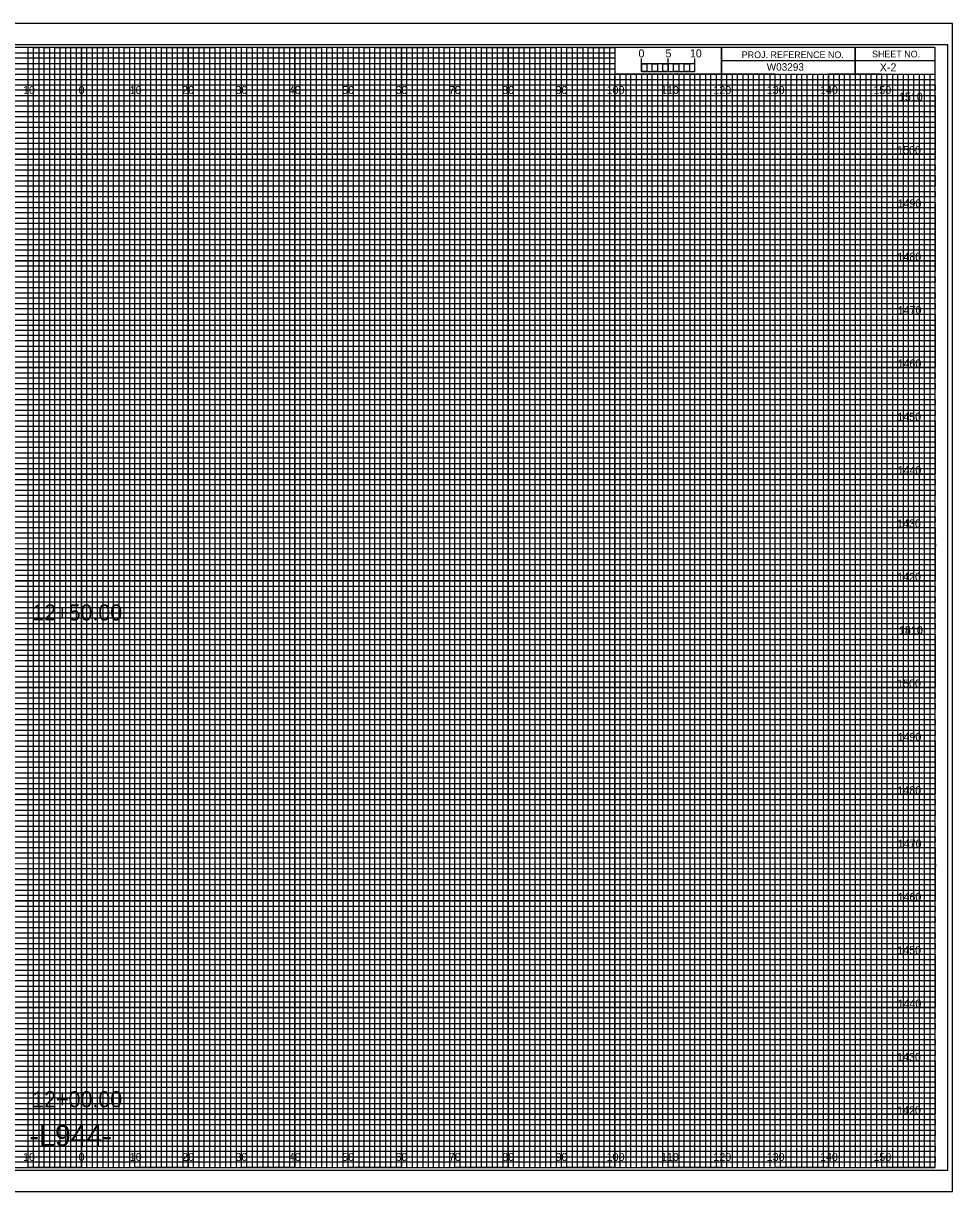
# Model space of a CAD drawing. Extents: x -13 to 323, y -5 to 215.
# Drawn here: x 149.1 to 323.3, y -4.5 to 214.5 of the extents above; entities that cross this region are included whole.
import ezdxf

# ---------------------------------------------------------------- set-up
doc = ezdxf.new("R2010")
doc.units = 0
for name, color, linetype in [('Exist Cross Section Cell', 7, 'Continuous'), ('Exist XS Center Line Elevation Label', 7, 'Continuous'), ('Exist XS Ground Line', 7, 'Continuous'), ('Prop XS Bar Scale Labels', 7, 'Continuous'), ('Prop XS EOT Tick Mark', 7, 'Continuous'), ('Prop XS Finish Grade', 7, 'Continuous'), ('Prop XS Finish Grade Earthwork', 7, 'Continuous'), ('Prop XS Finish Grade Pavement', 7, 'Continuous'), ('Prop XS Retaining Wall', 7, 'Continuous'), ('Prop XS SE Text', 7, 'Continuous'), ('Prop XS Side Slope Text', 7, 'Continuous'), ('Prop XS SS Elevation Text', 7, 'Continuous'), ('Prop XS Subgrade Earthwork', 7, 'Continuous'), ('Prop XSC Text', 7, 'Continuous'), ('Scratch_Level_5', 7, 'Continuous'), ('Typical Curb CELL', 7, 'Continuous'), ('Typical Guardrail CELL', 7, 'Continuous')]:
    doc.layers.add(name, color=color, linetype=linetype)

msp = doc.modelspace()

# ---------------------------------------------------------------- linework, layer by layer
at = {"layer": 'Exist Cross Section Cell'}
for points in [[(145, 0), (155, 0), (155, 210), (165, 210), (165, 0), (175, 0), (175, 210), (185, 210), (185, 0), (195, 0), (195, 210), (205, 210), (205, 0), (215, 0), (215, 210), (225, 210), (225, 0), (235, 0), (235, 210), (245, 210), (245, 0), (255, 0), (255, 210), (259.93, 210), (260, 210), (260, 205), (264.99, 205), (264.99, 0), (275, 0), (275, 205), (285, 205), (285, 0), (295, 0), (295, 205), (305, 205), (305, 0), (315, 0), (315, 205)], [(0, 205), (275, 205)], [(0, 185), (320, 185), (320, 195), (0, 195)], [(0, 165), (320, 165), (320, 175), (0, 175)], [(0, 145), (320, 145), (320, 155), (0, 155)], [(0, 125), (320, 125), (320, 135), (0, 135)], [(0, 105), (320, 105), (320, 115), (0, 115)], [(0, 85), (320, 85), (320, 95), (0, 95)], [(0, 65), (320, 65), (320, 75), (0, 75)], [(0, 45), (320, 45), (320, 55), (0, 55)], [(0, 25), (320, 25), (320, 35), (0, 35)], [(0, 5), (320, 5), (320, 15), (0, 15)]]:
    msp.add_lwpolyline(points, dxfattribs=at)
at = {"layer": 'Exist XS Center Line Elevation Label'}
for p, q in [((150, 210), (140, 210)), ((150, 0), (150, 210)), ((170, 210), (160, 210)), ((160, 210), (160, 0)), ((170, 0), (170, 210)), ((190, 210), (180, 210)), ((180, 210), (180, 0)), ((190, 0), (190, 210)), ((210, 210), (200, 210)), ((200, 210), (200, 0)), ((210, 0), (210, 210)), ((230, 210), (220, 210)), ((220, 210), (220, 0)), ((230, 0), (230, 210)), ((250, 210), (240, 210)), ((240, 210), (240, 0)), ((250, 0), (250, 210)), ((260, 210), (260, 0)), ((270, 0), (270, 205)), ((290, 205), (280, 205)), ((280, 205), (280, 0)), ((290, 0), (290, 205)), ((310, 205), (300, 205)), ((300, 205), (300, 0)), ((310, 0), (310, 205)), ((160, 0), (150, 0)), ((180, 0), (170, 0)), ((200, 0), (190, 0)), ((220, 0), (210, 0)), ((240, 0), (230, 0)), ((260, 0), (250, 0)), ((280, 0), (270, 0)), ((300, 0), (290, 0)), ((320, 0), (310, 0)), ((320, 0), (320, 0))]:
    msp.add_line(p, q, dxfattribs=at)
for points in [[(0, 200), (320, 200), (320, 190), (0, 190)], [(0, 180), (320, 180), (320, 170), (0, 170)], [(0, 160), (320, 160), (320, 150), (0, 150)], [(0, 140), (320, 140), (320, 130), (0, 130)], [(0, 120), (320, 120), (320, 110), (0, 110)], [(0, 100), (320, 100), (320, 90), (0, 90)], [(0, 80), (320, 80), (320, 70), (0, 70)], [(0, 60), (320, 60), (320, 50), (0, 50)], [(0, 40), (320, 40), (320, 30), (0, 30)], [(0, 20), (320, 20), (320, 10), (0, 10)]]:
    msp.add_lwpolyline(points, dxfattribs=at)
at = {"layer": 'Prop XS EOT Tick Mark'}
for p, q in [((323.3, 214.5), (-13.4, 214.5)), ((-13.4, -4.5), (323.3, -4.5))]:
    msp.add_line(p, q, dxfattribs=at)
at = {"layer": 'Prop XS Finish Grade'}
for p, q in [((150, 0), (150, 210)), ((160, 0), (160, 210)), ((170, 0), (170, 210)), ((180, 0), (180, 210)), ((190, 0), (190, 210)), ((200, 0), (200, 210)), ((210, 0), (210, 210)), ((220, 0), (220, 210)), ((230, 0), (230, 210)), ((240, 0), (240, 210)), ((250, 0), (250, 210)), ((260, 0), (260, 204.69)), ((270, 0), (270, 204.69)), ((280, 0), (280, 204.69)), ((290, 0), (290, 204.69)), ((300, 0), (300, 204.69)), ((310, 0), (310, 204.69)), ((0, 200), (320, 200)), ((0, 190), (320, 190)), ((0, 180), (320, 180)), ((0, 170), (320, 170)), ((0, 160), (320, 160)), ((0, 150), (320, 150)), ((0, 140), (320, 140)), ((0, 130), (320, 130)), ((0, 120), (320, 120)), ((0, 110), (320, 110)), ((0, 100), (320, 100)), ((0, 90), (320, 90)), ((0, 80), (320, 80)), ((0, 70), (320, 70)), ((0, 60), (320, 60)), ((0, 50), (320, 50)), ((0, 40), (320, 40)), ((0, 30), (320, 30)), ((0, 20), (320, 20)), ((0, 10), (320, 10))]:
    msp.add_line(p, q, dxfattribs=at)
at = {"layer": 'Prop XS Finish Grade Pavement'}
for p, q in [((265, 205.49), (265, 207.9)), ((265, 206.9), (265, 207.9)), ((270, 205.49), (270, 207.9)), ((275, 205.49), (275, 207.9)), ((275, 206.9), (275, 207.9))]:
    msp.add_line(p, q, dxfattribs=at)
for points in [[(275, 206.9), (265, 206.9), (265, 205.49), (275, 205.49)], [(265, 206.9), (266, 206.9), (266, 205.49), (265, 205.49)], [(267, 206.9), (268, 206.9), (268, 205.49), (267, 205.49)], [(269, 206.9), (270, 206.9), (270, 205.49), (269, 205.49)], [(271, 206.9), (272, 206.9), (272, 205.49), (271, 205.49)], [(273, 206.9), (274, 206.9), (274, 205.49), (273, 205.49)]]:
    msp.add_lwpolyline(points, close=True, dxfattribs=at)
at = {"layer": 'Prop XS SE Text'}
for p, q in [((267, 205), (266.01, 205)), ((266.01, 205), (266.01, 0)), ((267, 0), (267, 205)), ((269, 205), (268, 205)), ((268, 205), (268, 0)), ((269, 0), (269, 205)), ((266.01, 0), (265, 0)), ((268, 0), (267, 0))]:
    msp.add_line(p, q, dxfattribs=at)
for points in [[(150, 0), (151, 0), (151, 210), (152, 210), (152, 0)], [(152, 0), (153, 0), (153, 210), (154, 210), (154, 0)], [(155, 0), (156, 0), (156, 210), (157, 210), (157, 0)], [(157, 0), (158, 0), (158, 210), (159, 210), (159, 0)], [(160, 0), (161, 0), (161, 210), (162, 210), (162, 0)], [(162, 0), (163, 0), (163, 210), (164, 210), (164, 0)], [(165, 0), (166, 0), (166, 210), (167, 210), (167, 0)], [(167, 0), (168, 0), (168, 210), (169, 210), (169, 0)], [(170, 0), (171, 0), (171, 210), (172, 210), (172, 0)], [(172, 0), (173, 0), (173, 210), (174, 210), (174, 0)], [(175, 0), (176, 0), (176, 210), (177, 210), (177, 0)], [(177, 0), (178, 0), (178, 210), (179, 210), (179, 0)], [(180, 0), (181, 0), (181, 210), (182, 210), (182, 0)], [(182, 0), (183, 0), (183, 210), (184, 210), (184, 0)], [(185, 0), (186, 0), (186, 210), (187, 210), (187, 0)], [(187, 0), (188, 0), (188, 210), (189, 210), (189, 0)], [(190, 0), (191, 0), (191, 210), (192, 210), (192, 0)], [(192, 0), (193, 0), (193, 210), (194, 210), (194, 0)], [(195, 0), (196, 0), (196, 210), (197, 210), (197, 0)], [(197, 0), (198, 0), (198, 210), (199, 210), (199, 0)], [(200, 0), (201, 0), (201, 210), (202, 210), (202, 0)], [(202, 0), (203, 0), (203, 210), (204, 210), (204, 0)], [(205, 0), (206, 0), (206, 210), (207, 210), (207, 0)], [(207, 0), (208, 0), (208, 210), (209, 210), (209, 0)], [(210, 0), (211, 0), (211, 210), (212, 210), (212, 0)], [(212, 0), (213, 0), (213, 210), (214, 210), (214, 0)], [(215, 0), (216, 0), (216, 210), (217, 210), (217, 0)], [(217, 0), (218, 0), (218, 210), (219, 210), (219, 0)], [(220, 0), (221, 0), (221, 210), (222, 210), (222, 0)], [(222, 0), (223, 0), (223, 210), (224, 210), (224, 0)], [(225, 0), (226, 0), (226, 210), (227, 210), (227, 0)], [(227, 0), (228, 0), (228, 210), (229, 210), (229, 0)], [(230, 0), (231, 0), (231, 210), (232, 210), (232, 0)], [(232, 0), (233, 0), (233, 210), (234, 210), (234, 0)], [(235, 0), (236, 0), (236, 210), (237, 210), (237, 0)], [(237, 0), (238, 0), (238, 210), (239, 210), (239, 0)], [(240, 0), (241, 0), (241, 210), (242, 210), (242, 0)], [(242, 0), (243, 0), (243, 210), (244, 210), (244, 0)], [(245, 0), (246, 0), (246, 210), (247, 210), (247, 0)], [(247, 0), (248, 0), (248, 210), (249, 210), (249, 0)], [(250, 0), (251, 0), (251, 210), (252, 210), (252, 0)], [(252, 0), (253, 0), (253, 210), (254, 210), (254, 0)], [(255, 0), (256, 0), (256, 210), (257, 210), (257, 0)], [(257, 0), (258, 0), (258, 210), (259, 210), (259, 0)], [(260, 0), (261, 0), (261, 205), (262.02, 205), (262.02, 0)], [(262, 0), (263, 0), (263, 205), (263.99, 205), (263.99, 0)], [(270, 0), (270.98, 0), (270.98, 205), (272, 205), (272, 0)], [(272, 0), (273, 0), (273, 205), (274.05, 205), (274.05, 0)], [(275, 0), (276, 0), (276, 205), (277, 205), (277, 0)], [(277, 0), (278, 0), (278, 205), (279, 205), (279, 0)], [(280, 0), (281, 0), (281, 205), (282, 205), (282, 0)], [(282, 0), (283, 0), (283, 205), (284, 205), (284, 0)], [(285, 0), (286, 0), (286, 205), (287, 205), (287, 0)], [(287, 0), (288, 0), (288, 205), (289, 205), (289, 0)], [(290, 0), (291, 0), (291, 205), (292, 205), (292, 0)], [(292, 0), (293, 0), (293, 205), (294, 205), (294, 0)], [(295, 0), (296, 0), (296, 205), (297, 205), (297, 0)], [(297, 0), (298, 0), (298, 205), (299, 205), (299, 0)], [(300, 0), (301, 0), (301, 205), (302, 205), (302, 0)], [(302, 0), (303, 0), (303, 205), (304, 205), (304, 0)], [(305, 0), (306, 0), (306, 205), (307, 205), (307, 0)], [(307, 0), (308, 0), (308, 205), (309, 205), (309, 0)], [(310, 0), (311, 0), (311, 205), (312, 205), (312, 0)], [(312, 0), (313, 0), (313, 205), (314, 205), (314, 0)], [(315, 0), (316, 0), (316, 205), (317, 205), (317, 0)], [(317, 0), (318, 0), (318, 205), (319, 205), (319, 0)]]:
    msp.add_lwpolyline(points, dxfattribs=at)
at = {"layer": 'Prop XS Subgrade Earthwork'}
msp.add_lwpolyline([(-13.4, -4.5), (323.3, -4.5), (323.3, 214.5), (-13.4, 214.5)], close=True, dxfattribs=at)
at = {"layer": 'Prop XSC Text'}
for p, q in [((305, 210), (305, 205)), ((305, 205), (305, 210)), ((280, 207.5), (280, 205)), ((320, 207.49), (280, 207.49)), ((280, 205), (320, 205))]:
    msp.add_line(p, q, dxfattribs=at)
for points in [[(320, 210), (0, 210), (0, 0), (320, 0)], [(280, 210), (260, 210), (260, 205.03), (280, 205.03)], [(320, 210), (280, 210), (280, 205), (320, 205)]]:
    msp.add_lwpolyline(points, close=True, dxfattribs=at)
at = {"layer": 'Scratch_Level_5'}
for p, q in [((0, 209), (260, 209)), ((260, 209), (260, 207.98)), ((260, 207.98), (0, 207.98)), ((0, 207), (260, 207)), ((260, 205.89), (0, 205.89)), ((260, 207), (260, 205.89)), ((0, 204), (320, 204))]:
    msp.add_line(p, q, dxfattribs=at)
for points in [[(0, 203), (270, 203), (320, 203), (320, 202), (0, 202)], [(0, 201), (320, 201), (320, 199), (0, 199)], [(0, 198), (320, 198), (320, 197), (0, 196.98)], [(0, 196), (320, 196), (320, 194), (0, 194)], [(0, 193), (320, 193), (320, 192), (0, 192)], [(0, 191), (320, 191), (320, 189), (0, 189)], [(0, 188), (320, 188), (320, 187), (0, 187)], [(0, 186), (320, 186), (320, 184), (0, 184)], [(0, 183), (320, 183), (320, 182), (0, 182)], [(0, 181), (320, 181), (320, 179), (0, 179)], [(0, 178), (320, 178), (320, 177), (0, 177)], [(0, 176), (320, 176), (320, 173.95), (320, 173), (320, 172), (0, 172)], [(0, 174), (320, 174), (320, 173), (0, 173)], [(0, 171), (320, 171), (320, 169), (0, 169.03)], [(0, 169.03), (320, 169), (320, 168), (0, 168)], [(0, 167), (320, 167), (320, 166), (0, 166)], [(0, 164), (320, 164), (320, 163), (0, 163)], [(0, 162), (320, 162), (320, 161), (0, 161)], [(-0.07, 158.89), (320, 158.89), (320, 157.88), (-0.07, 157.88)], [(0, 157), (320, 157), (320, 156), (0, 156)], [(0, 154), (320, 154), (320, 153), (0, 153)], [(0, 152), (320, 152), (320, 151), (0, 151)], [(0, 149), (320, 149), (320, 148), (0, 148)], [(0, 147), (320, 147), (320, 146), (0, 146)], [(0, 144), (320, 144), (320, 143), (0, 143)], [(0, 142), (320, 142), (320, 141), (0, 141)], [(0, 139), (320, 139), (319.99, 137.98), (0, 138)], [(0, 137), (320, 137), (320, 136), (0, 136)], [(0, 134), (320, 134), (320, 133), (0, 133)], [(0, 132), (320, 132), (320, 131), (0, 131)], [(0, 129), (320, 129), (320, 128), (0, 128)], [(0, 127), (320, 127), (320, 126), (0, 126)], [(0, 124), (320, 124), (320, 123), (0, 123)], [(0, 122), (320, 122), (320, 121), (0, 121)], [(0, 119), (320, 119), (320, 118), (0, 118)], [(0, 116.99), (320.07, 116.91), (320, 116), (0, 116)], [(0, 114), (320, 114), (320, 113), (0, 113)], [(0, 112), (320, 112), (320, 111), (0, 111)], [(0, 109), (320, 109), (320, 108), (0, 108)], [(0, 107), (320, 107), (320, 106), (0, 106)], [(0, 104), (320, 104), (320, 103), (0, 103)], [(0, 102), (320, 102), (320, 101), (0, 101)], [(0, 99), (320, 99), (320, 98), (0, 98)], [(0, 97), (320, 97), (320, 96), (0, 96)], [(0, 94), (320, 94), (320, 93), (0, 93)], [(0, 92), (320, 92), (320, 91), (0, 91)], [(0, 89), (320, 89), (320, 88), (0, 88)], [(0, 87), (320, 87), (320, 86), (0, 86)], [(0, 84), (320, 84), (320, 83), (0, 83)], [(0, 82), (320, 82), (320, 81), (0, 81)], [(0, 79), (320, 79), (319.99, 77.98), (0, 78)], [(0, 77), (320, 77), (320, 76), (0, 76)], [(0, 74), (320, 74), (320, 73), (0, 73)], [(0, 72), (320, 72), (320, 71), (0, 71)], [(0, 69), (320, 69), (320, 68), (0, 68)], [(0, 67), (320, 67), (320, 66), (0, 66)], [(0, 64), (320, 64), (320, 63), (0, 63)], [(0, 62), (320, 62), (320, 61), (0, 61)], [(0, 59), (320, 59), (320, 58), (0, 58)], [(0, 56.99), (320.07, 56.91), (320, 56), (0, 56)], [(0, 54), (320, 54), (320, 53), (0, 53)], [(0, 52), (320, 52), (320, 51), (0, 51)], [(0, 49), (320, 49), (320, 48), (0, 48)], [(0, 47), (320, 47), (320, 46), (0, 46)], [(0, 44), (320, 44), (320, 43), (0, 43)], [(0, 42), (320, 42), (320, 41), (0, 41)], [(0, 39), (320, 39), (320, 38), (0, 38)], [(0, 37), (320, 37), (320, 36), (0, 36)], [(0, 34), (320, 34), (320, 33), (0, 33)], [(0, 32), (320, 32), (320, 31), (0, 31)], [(0, 29), (320, 29), (320, 28), (0, 28)], [(0, 27), (320, 27), (320, 26), (0, 26)], [(0, 24), (320, 24), (320, 23), (0, 23)], [(0, 22), (320, 22), (320, 21), (0, 21)], [(0, 19), (320, 19), (320, 18), (0, 18)], [(0, 17), (320, 17), (320, 16), (0, 16)], [(0, 14), (320, 14), (320, 13), (0, 13)], [(0, 12), (320, 12), (320, 11), (0, 11)], [(0, 9), (320, 9), (320, 8), (0, 8)], [(0, 7), (320, 7), (320, 6), (0, 6)], [(0, 4), (320, 4), (320, 3), (0, 3)], [(0, 2), (320, 2), (320, 1), (0, 1)]]:
    msp.add_lwpolyline(points, dxfattribs=at)
at = {"layer": 'Typical Curb CELL'}
msp.add_lwpolyline([(-10.8, -0.5), (322.4, -0.5), (322.4, 210.5), (-10.8, 210.5)], close=True, dxfattribs=at)

# ---------------------------------------------------------------- texts
at = {"layer": 'Exist XS Ground Line'}
for s, p in [('10', (149.04, 201.25)), ('0', (159.45, 201.25)), ('0', (159.45, 201.25)), ('10', (169.04, 201.25)), ('20', (178.86, 201.25)), ('30', (188.86, 201.25)), ('40', (198.86, 201.25)), ('50', (208.86, 201.25)), ('60', (218.86, 201.25)), ('70', (228.86, 201.25)), ('80', (238.86, 201.25)), ('90', (248.86, 201.25)), ('100', (258.44, 201.25)), ('110', (268.62, 201.25)), ('120', (278.44, 201.25)), ('130', (288.44, 201.25)), ('140', (298.44, 201.25)), ('150', (308.44, 201.25)), ('10', (149.04, 1.25)), ('0', (159.45, 1.25)), ('0', (159.45, 1.25)), ('10', (169.04, 1.25)), ('20', (178.86, 1.25)), ('30', (188.86, 1.25)), ('40', (198.86, 1.25)), ('50', (208.86, 1.25)), ('60', (218.86, 1.25)), ('70', (228.86, 1.25)), ('80', (238.86, 1.25)), ('90', (248.86, 1.25)), ('100', (258.44, 1.25)), ('110', (268.62, 1.25)), ('120', (278.44, 1.25)), ('130', (288.44, 1.25)), ('140', (298.44, 1.25)), ('150', (308.44, 1.25))]:
    msp.add_text(s, height=1.5, dxfattribs=at).set_placement(p)
at = {"layer": 'Prop XS Bar Scale Labels'}
for s, p in [('5', (269.47, 208.12)), ('10', (274.04, 208.12))]:
    msp.add_text(s, height=1.5, dxfattribs=at).set_placement(p)
at = {"layer": 'Prop XS Finish Grade Earthwork'}
for s, p in [('12+50.00', (150.77, 102.57)), ('12+00.00', (150.77, 11.32))]:
    msp.add_text(s, height=3, dxfattribs=at).set_placement(p)
at = {"layer": 'Prop XS Finish Grade Pavement'}
msp.add_text('0', height=1.5, dxfattribs=at).set_placement((264.41, 208.12))
at = {"layer": 'Prop XS Retaining Wall'}
msp.add_text('X-2', height=1.5, dxfattribs=at).set_placement((309.64, 205.5))
at = {"layer": 'Prop XS Side Slope Text'}
msp.add_text('W03293', height=1.4, dxfattribs=at).set_placement((288.45, 205.63))
at = {"layer": 'Prop XS SS Elevation Text'}
msp.add_text('-L944-', height=4, dxfattribs=at).set_placement((150.25, 4))
at = {"layer": 'Prop XSC Text'}
for s, p in [('PROJ. REFERENCE NO.', (283.77, 207.99)), ('SHEET NO.', (308.19, 208.12))]:
    msp.add_text(s, height=1.25, dxfattribs=at).set_placement(p)
at = {"layer": 'Typical Guardrail CELL'}
for s, p in [('1510', (313.23, 200)), ('1500', (312.9, 190)), ('1490', (312.97, 180)), ('1480', (312.95, 170)), ('1470', (313, 160)), ('1460', (312.97, 150)), ('1450', (312.92, 140)), ('1440', (312.97, 130)), ('1430', (312.89, 120)), ('1420', (312.9, 110)), ('1510', (313.23, 100)), ('1410', (313.28, 100)), ('1500', (312.9, 90)), ('1490', (312.97, 80)), ('1480', (312.95, 70)), ('1470', (313, 60)), ('1460', (312.97, 50)), ('1450', (312.92, 40)), ('1440', (312.97, 30)), ('1430', (312.89, 20)), ('1420', (312.9, 10))]:
    msp.add_text(s, height=1.5, dxfattribs=at).set_placement(p)

doc.saveas('drawing.dxf')
